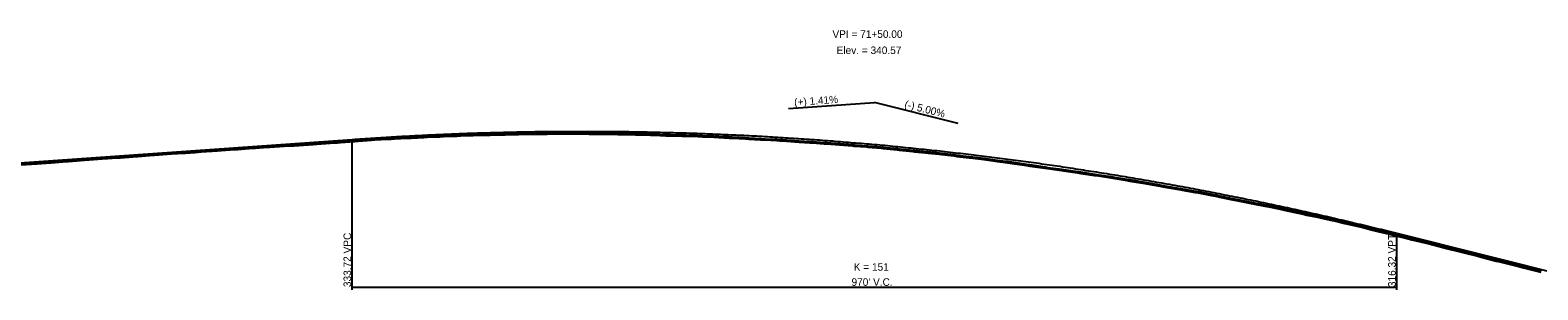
# Model space of a CAD drawing. Extents: x 1876258 to 1932803, y 754739 to 837911.
# Drawn here: x 1884729 to 1886129, y 831533 to 831774 of the extents above; entities that cross this region are included whole.
import ezdxf

# ---------------------------------------------------------------- set-up
doc = ezdxf.new("R2010")
doc.units = 0
for name, color, linetype in [('RD_DDB_GradeTX', 7, 'Continuous'), ('RD_DDB_Profile_EX', 7, 'Continuous'), ('RD_DDB_Profile_Lbl', 7, 'Continuous'), ('RD_DDB_Profile_PR', 7, 'Continuous'), ('RD_DDB_StripGrade', 7, 'Continuous'), ('RD_DDB_VCLbl', 7, 'Continuous'), ('RD_Sketch1', 7, 'Continuous')]:
    doc.layers.add(name, color=color, linetype=linetype)

msp = doc.modelspace()

# ---------------------------------------------------------------- linework, layer by layer
at = {"layer": 'RD_DDB_GradeTX'}
for p in [(1885433.3, 831701.5), (1885590.7, 831687.7)]:
    msp.add_line(p, (1885513.1, 831707.1), dxfattribs=at)
at = {"layer": 'RD_DDB_Profile_EX'}
for points in [[(1884720.5, 831649.3), (1884730.4, 831650), (1884735.6, 831650.4), (1884744, 831651), (1884748.5, 831651.3), (1884759.6, 831652.2), (1884764.6, 831652.5), (1884779.5, 831653.6), (1884784, 831653.9), (1884796, 831654.8), (1884801.1, 831655.1), (1884809.7, 831655.7), (1884813.1, 831655.9), (1884824.6, 831656.8), (1884829, 831657.1), (1884839.9, 831657.9), (1884844.5, 831658.3), (1884856.4, 831659.2), (1884860.3, 831659.5), (1884871.6, 831660.2), (1884873.5, 831660.3), (1884882.3, 831660.9), (1884888, 831661.4), (1884903.1, 831662.4), (1884906.4, 831662.6), (1884918.8, 831663.5), (1884922, 831663.7), (1884935.8, 831664.7), (1884938.4, 831664.9), (1884949.5, 831665.6), (1884951.6, 831665.7), (1884969.6, 831666.9), (1884971.9, 831667), (1884974.2, 831667.1), (1884991.9, 831668.1), (1884995.2, 831668.4), (1885012, 831669.7), (1885014.5, 831669.9), (1885017.3, 831670.1), (1885030.3, 831671.1), (1885033.8, 831671.3), (1885046, 831672.2), (1885049.2, 831672.4), (1885061.3, 831673.1), (1885064.3, 831673.2), (1885067.3, 831673.4), (1885079.3, 831674), (1885083, 831674.2), (1885094.8, 831674.8), (1885097.7, 831674.9), (1885109.6, 831675.4), (1885112.9, 831675.6), (1885125.3, 831676), (1885128.8, 831676.2), (1885138.2, 831676.4), (1885140.6, 831676.5), (1885153.8, 831676.9), (1885156.2, 831677), (1885167.5, 831677.1), (1885170.2, 831677.2), (1885179, 831677.5), (1885182.6, 831677.5), (1885191.9, 831677.7), (1885195, 831677.7), (1885205.1, 831677.8), (1885209.2, 831677.8), (1885220, 831678), (1885223.2, 831678), (1885233, 831678), (1885236.1, 831678), (1885245.3, 831678), (1885248.1, 831677.9), (1885257.1, 831677.7), (1885260.2, 831677.7), (1885274.8, 831677.5), (1885278, 831677.4), (1885287.7, 831677.4), (1885291.3, 831677.3), (1885301.3, 831677.1), (1885305, 831677), (1885308.5, 831676.8), (1885319.4, 831676.3), (1885323.8, 831676.2), (1885334.4, 831676), (1885338.2, 831675.9), (1885349.4, 831675.5), (1885353.4, 831675.3), (1885364.4, 831674.9), (1885368.6, 831674.7), (1885378.3, 831674.2), (1885381, 831674.1), (1885393.5, 831673.5), (1885396.5, 831673.3), (1885407.4, 831672.6)], [(1885407.4, 831672.6), (1885411.4, 831672.4), (1885422.4, 831671.8), (1885425.2, 831671.6), (1885427.7, 831671.5), (1885439.2, 831670.8), (1885443.2, 831670.5), (1885453.1, 831669.8), (1885455.7, 831669.6), (1885466.5, 831668.9), (1885468.7, 831668.8), (1885480.7, 831667.9), (1885492.8, 831666.9), (1885493.7, 831666.9), (1885494.4, 831666.8), (1885505.6, 831665.9), (1885507, 831665.8), (1885519.2, 831664.7), (1885521.2, 831664.5), (1885534.3, 831663.2), (1885534.5, 831663.2), (1885535.9, 831663), (1885548.7, 831661.7), (1885550.4, 831661.5), (1885560.5, 831660.6), (1885563, 831660.3), (1885573.3, 831659.2), (1885575.8, 831659), (1885586.8, 831657.6), (1885589.7, 831657.2), (1885600.9, 831655.9), (1885604.4, 831655.4), (1885614.6, 831654.4), (1885616.7, 831654.1), (1885629.4, 831652.2), (1885632.2, 831651.9), (1885636.5, 831651.3), (1885654.2, 831648.7), (1885657.3, 831648.2), (1885671.3, 831646.2), (1885673.9, 831645.8), (1885686.9, 831644), (1885688.6, 831643.7), (1885701.6, 831641.9), (1885703.1, 831641.6), (1885704.6, 831641.4), (1885717.5, 831639.5), (1885719.2, 831639.3), (1885732.6, 831637.2), (1885734.3, 831636.9), (1885747.3, 831634.8), (1885748.8, 831634.6), (1885750.2, 831634.3), (1885764.1, 831632.1), (1885765.7, 831631.8), (1885778, 831629.5), (1885779.5, 831629.3), (1885780.9, 831629), (1885797.6, 831626.2), (1885798.8, 831625.9), (1885810.9, 831623.8), (1885813.8, 831623.3), (1885826.2, 831620.9), (1885829.8, 831620.2), (1885833.4, 831619.4), (1885845.6, 831617), (1885849, 831616.3), (1885859.9, 831614), (1885864.4, 831613.2), (1885875.5, 831611.1), (1885879.3, 831610.3), (1885889.9, 831608.1), (1885893.6, 831607.3), (1885906.5, 831604.6), (1885910, 831603.8), (1885914.7, 831602.8), (1885924.6, 831600.7), (1885928.3, 831599.9), (1885938, 831597.7), (1885941.5, 831597), (1885949.9, 831595), (1885952.7, 831594.3), (1885963.7, 831591.8), (1885966.6, 831591.1), (1885975.7, 831588.8), (1885980.5, 831587.6), (1885991.3, 831584.9), (1885995.9, 831583.8), (1886007.5, 831581), (1886012.1, 831579.9), (1886024.3, 831576.9), (1886028.3, 831575.9), (1886040.8, 831572.7), (1886044.4, 831571.8), (1886056.9, 831568.6), (1886060.7, 831567.7), (1886073.4, 831564.5), (1886076.6, 831563.7), (1886090.5, 831560.1), (1886093.8, 831559.3), (1886108.7, 831555.7)], [(1886108.7, 831555.7), (1886112.3, 831554.8), (1886115.9, 831553.9), (1886132, 831549.7)]]:
    msp.add_lwpolyline(points, dxfattribs=at)
at = {"layer": 'RD_DDB_Profile_PR'}
for p, q in [((1884343.1, 831624.5), (1885028.1, 831672.9)), ((1885998.1, 831585.9), (1886165.1, 831544.1))]:
    msp.add_line(p, q, dxfattribs=at)
msp.add_spline([(1885028.1, 831672.9), (1885047.5, 831674.2), (1885066.9, 831675.4), (1885086.3, 831676.4), (1885105.7, 831677.4), (1885125.1, 831678.2), (1885144.5, 831678.9), (1885163.9, 831679.4), (1885183.3, 831679.9), (1885202.7, 831680.2), (1885222.1, 831680.4), (1885241.5, 831680.4), (1885260.9, 831680.4), (1885280.3, 831680.2), (1885299.7, 831679.9), (1885319.1, 831679.4), (1885338.5, 831678.9), (1885357.9, 831678.2), (1885377.3, 831677.4), (1885396.7, 831676.5), (1885416.1, 831675.4), (1885435.5, 831674.2), (1885454.9, 831672.9), (1885474.3, 831671.5), (1885493.7, 831669.9), (1885513.1, 831668.3), (1885532.5, 831666.5), (1885551.9, 831664.5), (1885571.3, 831662.5), (1885590.7, 831660.3), (1885610.1, 831658), (1885629.5, 831655.6), (1885648.9, 831653), (1885668.3, 831650.4), (1885687.7, 831647.6), (1885707.1, 831644.6), (1885726.5, 831641.6), (1885745.9, 831638.4), (1885765.3, 831635.1), (1885784.7, 831631.7), (1885804.1, 831628.2), (1885823.5, 831624.5), (1885842.9, 831620.7), (1885862.3, 831616.8), (1885881.7, 831612.8), (1885901.1, 831608.6), (1885920.5, 831604.3), (1885939.9, 831599.9), (1885959.3, 831595.3), (1885978.7, 831590.7), (1885998.1, 831585.9)], degree=3, dxfattribs=at)
at = {"layer": 'RD_DDB_VCLbl'}
for p, q in [((1885028.1, 831533.4), (1885028.1, 831672.9)), ((1885998.1, 831533.4), (1885998.1, 831585.9)), ((1885028.1, 831535.9), (1885998.1, 831535.9))]:
    msp.add_line(p, q, dxfattribs=at)
at = {"layer": 'RD_Sketch1'}
msp.add_lwpolyline([(1884720.4, 831650.6), (1884730.3, 831651.2), (1884735.5, 831651.6), (1884743.9, 831652.2), (1884748.4, 831652.6), (1884759.5, 831653.4), (1884764.5, 831653.8), (1884779.4, 831654.8), (1884783.9, 831655.1), (1884795.9, 831656), (1884801, 831656.3), (1884809.6, 831656.9), (1884813, 831657.2), (1884824.5, 831658.1), (1884828.9, 831658.4), (1884839.8, 831659.1), (1884844.4, 831659.5), (1884856.3, 831660.4), (1884860.2, 831660.7), (1884871.5, 831661.4), (1884873.4, 831661.6), (1884882.2, 831662.2), (1884887.9, 831662.6), (1884903, 831663.6), (1884906.3, 831663.9), (1884918.7, 831664.8), (1884921.9, 831665), (1884935.7, 831666), (1884938.3, 831666.1), (1884949.4, 831666.9), (1884951.6, 831667), (1884969.5, 831668.1), (1884971.8, 831668.3), (1884974.1, 831668.4), (1884991.8, 831669.4), (1884995.1, 831669.6), (1885012, 831671), (1885014.4, 831671.1), (1885017.2, 831671.4), (1885030.2, 831672.3), (1885033.7, 831672.6), (1885045.9, 831673.4), (1885049.1, 831673.6), (1885061.2, 831674.3), (1885064.2, 831674.5), (1885067.2, 831674.6), (1885079.2, 831675.3), (1885083, 831675.5), (1885094.8, 831676), (1885097.7, 831676.1), (1885109.6, 831676.7), (1885112.8, 831676.8), (1885125.3, 831677.3), (1885128.7, 831677.4), (1885138.2, 831677.7), (1885140.6, 831677.7), (1885153.7, 831678.2), (1885156.2, 831678.2), (1885167.5, 831678.4), (1885170.1, 831678.4), (1885179, 831678.7), (1885182.5, 831678.8), (1885191.9, 831678.9), (1885195, 831679), (1885205.1, 831679), (1885209.2, 831679.1), (1885220, 831679.2), (1885223.2, 831679.2), (1885233, 831679.2), (1885236.1, 831679.3), (1885245.3, 831679.2), (1885248.1, 831679.2), (1885257.1, 831679), (1885260.2, 831678.9), (1885274.8, 831678.7), (1885278, 831678.7), (1885287.7, 831678.6), (1885291.3, 831678.6), (1885301.4, 831678.3), (1885305, 831678.2), (1885308.6, 831678.1), (1885319.5, 831677.6), (1885323.8, 831677.5), (1885334.5, 831677.3), (1885338.2, 831677.2), (1885349.5, 831676.8), (1885353.4, 831676.6), (1885364.4, 831676.1), (1885368.6, 831675.9), (1885378.3, 831675.5), (1885381, 831675.3), (1885393.5, 831674.7), (1885396.6, 831674.5), (1885407.5, 831673.8), (1885411.5, 831673.6), (1885422.5, 831673), (1885425.3, 831672.9), (1885427.8, 831672.7), (1885439.3, 831672), (1885443.3, 831671.7), (1885453.1, 831671.1), (1885455.8, 831670.9), (1885466.5, 831670.2), (1885468.7, 831670), (1885480.8, 831669.1), (1885492.9, 831668.2), (1885493.8, 831668.1), (1885494.6, 831668), (1885505.7, 831667.1), (1885507.1, 831667), (1885519.3, 831665.9), (1885521.3, 831665.8), (1885534.3, 831664.4), (1885534.5, 831664.4), (1885536, 831664.3), (1885548.8, 831662.9), (1885550.5, 831662.8), (1885560.6, 831661.8), (1885563.1, 831661.6), (1885573.4, 831660.5), (1885576, 831660.2), (1885586.9, 831658.8), (1885589.8, 831658.4), (1885601.1, 831657.1), (1885604.6, 831656.7), (1885614.8, 831655.6), (1885616.9, 831655.3), (1885629.6, 831653.5), (1885632.4, 831653.1), (1885636.6, 831652.6), (1885654.4, 831649.9), (1885657.5, 831649.5), (1885671.5, 831647.4), (1885674.1, 831647), (1885687.1, 831645.2), (1885688.8, 831645), (1885701.8, 831643.1), (1885703.3, 831642.9), (1885704.8, 831642.7), (1885717.7, 831640.8), (1885719.4, 831640.5), (1885732.8, 831638.4), (1885734.5, 831638.1), (1885747.5, 831636.1), (1885749, 831635.8), (1885750.4, 831635.6), (1885764.2, 831633.3), (1885765.9, 831633.1), (1885778.2, 831630.8), (1885779.7, 831630.5), (1885781.1, 831630.3), (1885797.9, 831627.4), (1885799, 831627.2), (1885811.1, 831625), (1885814, 831624.5), (1885826.4, 831622.1), (1885830, 831621.4), (1885833.7, 831620.6), (1885845.9, 831618.2), (1885849.2, 831617.5), (1885860.2, 831615.2), (1885864.7, 831614.4), (1885875.8, 831612.3), (1885879.6, 831611.5), (1885890.1, 831609.3), (1885893.8, 831608.5), (1885906.8, 831605.8), (1885910.3, 831605), (1885915, 831604), (1885924.9, 831601.9), (1885928.6, 831601.1), (1885938.3, 831598.9), (1885941.8, 831598.2), (1885950.2, 831596.2), (1885953, 831595.5), (1885964, 831593), (1885966.9, 831592.3), (1885976, 831590), (1885980.8, 831588.8), (1885991.6, 831586.1), (1885996.2, 831585), (1886007.8, 831582.3), (1886012.4, 831581.1), (1886024.6, 831578.1), (1886028.6, 831577.1), (1886041.1, 831573.9), (1886044.7, 831573), (1886057.2, 831569.8), (1886061, 831568.9), (1886073.7, 831565.8), (1886077, 831564.9), (1886090.8, 831561.4), (1886094.1, 831560.5), (1886109, 831556.9), (1886112.6, 831556), (1886116.2, 831555.1), (1886132.3, 831550.9)], dxfattribs=at)

# ---------------------------------------------------------------- texts
at = {"layer": 'RD_DDB_GradeTX'}
for s, rotation, p in [('(+) 1.41%', 4.041, (1885438.8, 831703.9)), ('(-) 5.00%', 345.9638, (1885540.4, 831702.4))]:
    msp.add_text(s, height=7, rotation=rotation, dxfattribs=at).set_placement(p)
at = {"layer": 'RD_DDB_Profile_Lbl'}
for s, p in [('VPI = 71+50.00', (1885474.1, 831767.1)), ('Elev. = 340.57', (1885478, 831752.1))]:
    msp.add_text(s, height=7, dxfattribs=at).set_placement(p)
at = {"layer": 'RD_DDB_StripGrade'}
for s, p in [('333.72 VPC', (1885027.1, 831535.9)), ('316.32 VPT', (1885997.1, 831535.9))]:
    msp.add_text(s, height=7, rotation=90, dxfattribs=at).set_placement(p)
at = {"layer": 'RD_DDB_VCLbl'}
for s, p in [('K = 151', (1885493.9, 831551.1)), ("970' V.C.", (1885491.8, 831537.1))]:
    msp.add_text(s, height=7, dxfattribs=at).set_placement(p)

doc.saveas('drawing.dxf')
